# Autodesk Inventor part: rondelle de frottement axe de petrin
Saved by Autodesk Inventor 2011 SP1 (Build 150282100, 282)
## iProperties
Created: 2010-12
Part Number: rondelle de frottement axe de petrin
Document SubType Name: Modeling
Designer: eric
Density: 1 g/cm^3
Mass: 0.0412334 g
Surface Area: 1.9792 cm^2
Volume: 0.0412334 cm^3
Author: eric
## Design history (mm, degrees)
feature "Base1"
node "Solide1"
node "Corps solides"
node "Corps surfaciques"
